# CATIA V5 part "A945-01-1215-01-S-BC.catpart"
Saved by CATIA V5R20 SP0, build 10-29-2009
Part number: A945-01-1215-01-S-BC
Source: Unknown
Property "ARTICLENO": "A945-01-1215-01-S-BC"
Property "B": "125.000"
Property "BOMINFO": "A945-01-1215-01-S-BC"
Property "CODE": "A945-01-1215-01-S-BC"
Property "D1": "26.000"
Property "D2": "17.500"
Property "D5": "20.000"
Property "D6": "16.000"
Property "H": "57.000"
Property "H1": "44.000"
Property "H2": "60.000"
Property "H3": "28.000"
Property "L1": "150.000"
Property "L2": "25.000"
Property "L3": "0.000"
Property "L4": "100.000"
Property "L5": "55.000"
Property "L6": "45.000"
Property "LINA": "A945-01-1215-01-S-BC"
Property "N": "5.000"
Property "NB": "A945-01-1215-01-S-BC"
Property "NBSYN": " $CODE."
Property "NN": "A945-01"
Property "NT": "v driver sets replaceable inserts pisitive return"
Property "SUPPLIER": "CF"
Property "Z": "85.000"
Bounding box of the stored display mesh (mm): x -669.473 to -511.473, y 748.188 to 833.188, z 0 to 150
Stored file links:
  C:\Users\Utente\Desktop\3D files A945-01\A945-01-1215-01-S-BC.catpart
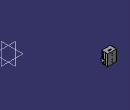
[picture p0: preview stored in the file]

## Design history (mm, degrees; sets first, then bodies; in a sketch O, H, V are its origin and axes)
Body1 "Geometry.1" (main body)
  Solid1 "A945-01-1215-01-S-BC.catpart": solid without history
